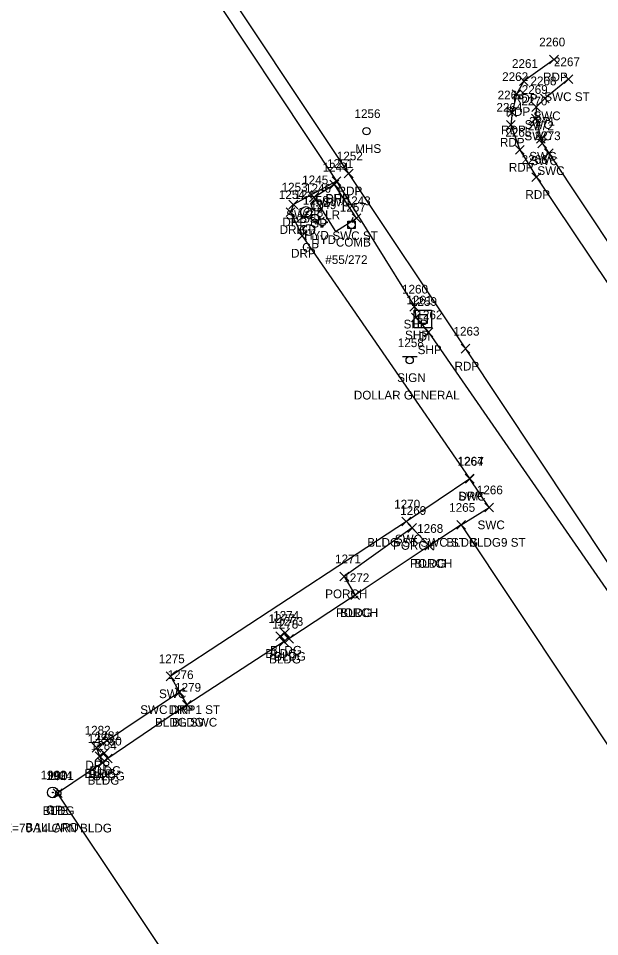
# Model space of a CAD drawing. Extents: x 1635588 to 1637550, y 621583 to 623638.
# Drawn here: x 1636661.5 to 1636794.5, y 622475 to 622685.3 of the extents above; entities that cross this region are included whole.
import ezdxf

# ---------------------------------------------------------------- set-up
doc = ezdxf.new("R2010")
doc.units = 0
for name, color, linetype in [('C_A', 7, 'Continuous'), ('C_C', 7, 'Continuous'), ('C_I', 7, 'Continuous'), ('CBP', 7, 'Continuous'), ('D_A', 7, 'Continuous'), ('D_I', 7, 'Continuous'), ('DS', 7, 'Continuous'), ('L_A', 7, 'Continuous'), ('L_I', 7, 'Continuous'), ('L_TIC', 7, 'Continuous'), ('LBC', 7, 'Continuous'), ('LBF', 7, 'Continuous'), ('P_A', 7, 'Continuous'), ('P_I', 7, 'Continuous'), ('P_TIC', 7, 'Continuous'), ('PET', 7, 'Continuous'), ('PSP', 7, 'Continuous'), ('R_A', 7, 'Continuous'), ('R_C', 7, 'Continuous'), ('R_I', 7, 'Continuous'), ('R_TIC', 7, 'Continuous'), ('RDP', 7, 'Continuous'), ('RGP', 7, 'Continuous'), ('RSW', 7, 'Continuous'), ('S_A', 7, 'Continuous'), ('S_C', 7, 'Continuous'), ('S_I', 7, 'Continuous'), ('SSGN', 7, 'Continuous'), ('U_A', 7, 'Continuous'), ('U_C', 7, 'Continuous'), ('U_I', 7, 'Continuous'), ('UP', 7, 'Continuous'), ('USMH', 7, 'Continuous'), ('UWFH', 7, 'Continuous')]:
    doc.layers.add(name, color=color, linetype=linetype)

msp = doc.modelspace()

# ---------------------------------------------------------------- linework, layer by layer
at = {"layer": 'CBP'}
for radius in [0.625, 0.0833]:
    msp.add_circle((1636670.59, 622507.85), radius, dxfattribs=at)
at = {"layer": 'DS'}
for p, q in [((1636752.05, 622618.47), (1636756.05, 622618.47)), ((1636752.05, 622614.47), (1636752.05, 622618.47)), ((1636756.05, 622618.47), (1636756.05, 622614.47)), ((1636753.05, 622615.47), (1636753.05, 622617.47)), ((1636753.05, 622617.47), (1636755.05, 622617.47)), ((1636754.06, 622616.47), (1636754.06, 622616.47)), ((1636754.06, 622616.47), (1636754.06, 622616.47)), ((1636755.05, 622617.47), (1636755.05, 622615.47)), ((1636756.05, 622614.47), (1636752.05, 622614.47)), ((1636755.05, 622615.47), (1636753.05, 622615.47))]:
    msp.add_line(p, q, dxfattribs=at)
at = {"layer": 'L_TIC'}
for points in [[(1636750.64, 622567.6), (1636752.64, 622569.6)], [(1636752.64, 622567.6), (1636750.64, 622569.6)], [(1636761.84, 622568.3), (1636763.84, 622570.3)], [(1636763.84, 622568.3), (1636761.84, 622570.3)], [(1636761.84, 622568.3), (1636763.84, 622570.3)], [(1636763.84, 622568.3), (1636761.84, 622570.3)], [(1636754.52, 622563.48), (1636756.52, 622565.48)], [(1636756.52, 622563.48), (1636754.52, 622565.48)], [(1636754.52, 622563.48), (1636756.52, 622565.48)], [(1636756.52, 622563.48), (1636754.52, 622565.48)], [(1636735.09, 622556.51), (1636737.09, 622558.51)], [(1636737.09, 622556.51), (1636735.09, 622558.51)], [(1636737.55, 622552.19), (1636739.55, 622554.19)], [(1636739.55, 622552.19), (1636737.55, 622554.19)], [(1636737.55, 622552.19), (1636739.55, 622554.19)], [(1636739.55, 622552.19), (1636737.55, 622554.19)], [(1636720.44, 622542.84), (1636722.44, 622544.84)], [(1636722.44, 622542.84), (1636720.44, 622544.84)], [(1636721.51, 622543.58), (1636723.51, 622545.58)], [(1636723.51, 622543.58), (1636721.51, 622545.58)], [(1636722.42, 622542.2), (1636724.42, 622544.2)], [(1636724.42, 622542.2), (1636722.42, 622544.2)], [(1636721.28, 622541.56), (1636723.28, 622543.56)], [(1636723.28, 622541.56), (1636721.28, 622543.56)], [(1636699.04, 622527.09), (1636701.04, 622529.09)], [(1636701.04, 622527.09), (1636699.04, 622529.09)], [(1636679.01, 622515.34), (1636681.01, 622517.34)], [(1636681.01, 622515.34), (1636679.01, 622517.34)], [(1636680.11, 622516.02), (1636682.11, 622518.02)], [(1636682.11, 622516.02), (1636680.11, 622518.02)], [(1636679.71, 622513.78), (1636681.71, 622515.78)], [(1636681.71, 622513.78), (1636679.71, 622515.78)], [(1636680.95, 622514.77), (1636682.95, 622516.77)], [(1636682.95, 622514.77), (1636680.95, 622516.77)], [(1636669.45, 622506.84), (1636671.45, 622508.84)], [(1636671.45, 622506.84), (1636669.45, 622508.84)]]:
    msp.add_lwpolyline(points, dxfattribs=at)
at = {"layer": 'LBC'}
for points in [[(1636762.84, 622569.3), (1636755.52, 622564.48), (1636738.55, 622553.19), (1636723.42, 622543.2), (1636722.51, 622544.58), (1636721.44, 622543.84), (1636722.28, 622542.56), (1636700.04, 622528.09), (1636681.95, 622515.77), (1636681.11, 622517.02), (1636680.01, 622516.34), (1636680.71, 622514.78)], [(1636762.84, 622569.3), (1636812.75, 622494.27), (1636839.75, 622454.02), (1636807.39, 622432.4)], [(1636680.71, 622514.78), (1636670.45, 622507.84)], [(1636729.47, 622348.39), (1636714.18, 622370.82), (1636701.75, 622403.63), (1636688.1, 622440.06), (1636687.15, 622442.65), (1636702.92, 622453.14), (1636705.64, 622455.02), (1636670.45, 622507.84)]]:
    msp.add_lwpolyline(points, dxfattribs=at)
at = {"layer": 'LBF'}
msp.add_lwpolyline([(1636755.52, 622564.48), (1636751.64, 622568.6), (1636736.09, 622557.51), (1636738.55, 622553.19)], dxfattribs=at)
at = {"layer": 'P_TIC'}
for points in [[(1636783.1, 622674.92), (1636785.1, 622676.92)], [(1636785.1, 622674.92), (1636783.1, 622676.92)], [(1636776.21, 622669.99), (1636778.21, 622671.99)], [(1636778.21, 622669.99), (1636776.21, 622671.99)], [(1636774.52, 622666.99), (1636776.52, 622668.99)], [(1636776.52, 622666.99), (1636774.52, 622668.99)], [(1636773.5, 622662.78), (1636775.5, 622664.78)], [(1636775.5, 622662.78), (1636773.5, 622664.78)], [(1636773.23, 622659.96), (1636775.23, 622661.96)], [(1636775.23, 622659.96), (1636773.23, 622661.96)], [(1636775.27, 622654.22), (1636777.27, 622656.22)], [(1636777.27, 622654.22), (1636775.27, 622656.22)], [(1636736.08, 622648.81), (1636738.08, 622650.81)], [(1636738.08, 622648.81), (1636736.08, 622650.81)], [(1636779.06, 622647.99), (1636781.06, 622649.99)], [(1636781.06, 622647.99), (1636779.06, 622649.99)], [(1636733.28, 622647.07), (1636735.28, 622649.07)], [(1636735.28, 622647.07), (1636733.28, 622649.07)], [(1636751.12, 622618.3), (1636753.12, 622620.3)], [(1636753.12, 622618.3), (1636751.12, 622620.3)], [(1636751.46, 622615.81), (1636753.46, 622617.81)], [(1636753.46, 622615.81), (1636751.46, 622617.81)], [(1636754.34, 622612.42), (1636756.34, 622614.42)], [(1636756.34, 622612.42), (1636754.34, 622614.42)], [(1636762.83, 622608.67), (1636764.83, 622610.67)], [(1636764.83, 622608.67), (1636762.83, 622610.67)]]:
    msp.add_lwpolyline(points, dxfattribs=at)
at = {"layer": 'PET'}
for points in [[(1636496.54, 623045.3), (1636533.69, 622970.65), (1636546.95, 622944.69), (1636557.06, 622926.23), (1636579, 622887.89), (1636603.72, 622849.48), (1636616.07, 622830.82), (1636647.79, 622783.76), (1636703.25, 622700.68), (1636737.08, 622649.81), (1636763.83, 622609.67), (1636812.95, 622535.62), (1636858.06, 622468.21), (1636878.24, 622438.26), (1636911.18, 622389.38), (1636974.88, 622293.33), (1636986.61, 622276.7), (1637016.63, 622231.99)], [(1636784.1, 622675.92), (1636777.21, 622670.99), (1636775.52, 622667.99), (1636774.5, 622663.78), (1636774.23, 622660.96), (1636776.27, 622655.22), (1636780.06, 622648.99), (1636825.5, 622581.26), (1636877.35, 622502.82), (1636883.38, 622494.85), (1636885.53, 622493.24), (1636887.72, 622493), (1636889.89, 622493.88)]]:
    msp.add_lwpolyline(points, dxfattribs=at)
at = {"layer": 'PSP'}
msp.add_lwpolyline([(1636412.61, 623220.07), (1636436.6, 623167.3), (1636456.23, 623125.07), (1636460.67, 623115.98), (1636475.52, 623084.87), (1636494.51, 623045.42), (1636524.16, 622986.51), (1636530.74, 622972.24), (1636554.07, 622925.3), (1636577.18, 622886.3), (1636601.72, 622847.41), (1636613.46, 622830.09), (1636645.38, 622782.47), (1636700.61, 622698.86), (1636734.28, 622648.07), (1636752.12, 622619.3), (1636752.46, 622616.81), (1636755.34, 622613.42), (1636810.04, 622534.39), (1636855.63, 622465.66), (1636874.76, 622437.49), (1636904.15, 622393.55)], dxfattribs=at)
at = {"layer": 'R_TIC'}
for points in [[(1636786.39, 622670.39), (1636788.39, 622672.39)], [(1636788.39, 622670.39), (1636786.39, 622672.39)], [(1636781.02, 622666.01), (1636783.02, 622668.01)], [(1636783.02, 622666.01), (1636781.02, 622668.01)], [(1636779.03, 622664.03), (1636781.03, 622666.03)], [(1636781.03, 622664.03), (1636779.03, 622666.03)], [(1636778.97, 622661.41), (1636780.97, 622663.41)], [(1636780.97, 622661.41), (1636778.97, 622663.41)], [(1636780.07, 622656.75), (1636782.07, 622658.75)], [(1636782.07, 622656.75), (1636780.07, 622658.75)], [(1636780.38, 622655.72), (1636782.38, 622657.72)], [(1636782.38, 622655.72), (1636780.38, 622657.72)], [(1636781.93, 622653.45), (1636783.93, 622655.45)], [(1636783.93, 622653.45), (1636781.93, 622655.45)], [(1636732.81, 622646.26), (1636734.81, 622648.26)], [(1636734.81, 622646.26), (1636732.81, 622648.26)], [(1636733.28, 622647.07), (1636735.28, 622649.07)], [(1636735.28, 622647.07), (1636733.28, 622649.07)], [(1636728.15, 622643.34), (1636730.15, 622645.34)], [(1636730.15, 622643.34), (1636728.15, 622645.34)], [(1636723.42, 622641.67), (1636725.42, 622643.67)], [(1636725.42, 622641.67), (1636723.42, 622643.67)], [(1636722.79, 622639.96), (1636724.79, 622641.96)], [(1636724.79, 622639.96), (1636722.79, 622641.96)], [(1636737.86, 622638.54), (1636739.86, 622640.54)], [(1636739.86, 622638.54), (1636737.86, 622640.54)], [(1636725.41, 622634.54), (1636727.41, 622636.54)], [(1636727.41, 622634.54), (1636725.41, 622636.54)], [(1636763.74, 622578.91), (1636765.74, 622580.91)], [(1636765.74, 622578.91), (1636763.74, 622580.91)], [(1636763.82, 622578.85), (1636765.82, 622580.85)], [(1636765.82, 622578.85), (1636763.82, 622580.85)], [(1636768.23, 622572.31), (1636770.23, 622574.31)], [(1636770.23, 622572.31), (1636768.23, 622574.31)], [(1636749.29, 622569.06), (1636751.29, 622571.06)], [(1636751.29, 622569.06), (1636749.29, 622571.06)], [(1636761.84, 622568.3), (1636763.84, 622570.3)], [(1636763.84, 622568.3), (1636761.84, 622570.3)], [(1636695.29, 622533.62), (1636697.29, 622535.62)], [(1636697.29, 622533.62), (1636695.29, 622535.62)], [(1636697.36, 622529.98), (1636699.36, 622531.98)], [(1636699.36, 622529.98), (1636697.36, 622531.98)], [(1636697.36, 622529.98), (1636699.36, 622531.98)], [(1636699.36, 622529.98), (1636697.36, 622531.98)], [(1636699.04, 622527.09), (1636701.04, 622529.09)], [(1636701.04, 622527.09), (1636699.04, 622529.09)], [(1636678.32, 622517.27), (1636680.32, 622519.27)], [(1636680.32, 622517.27), (1636678.32, 622519.27)], [(1636679.01, 622515.34), (1636681.01, 622517.34)], [(1636681.01, 622515.34), (1636679.01, 622517.34)]]:
    msp.add_lwpolyline(points, dxfattribs=at)
at = {"layer": 'RDP'}
for points in [[(1636734.28, 622648.07), (1636724.42, 622642.67), (1636723.79, 622640.96), (1636726.41, 622635.54), (1636764.74, 622579.91)], [(1636698.36, 622530.98), (1636679.32, 622518.27), (1636680.01, 622516.34)]]:
    msp.add_lwpolyline(points, dxfattribs=at)
at = {"layer": 'RGP'}
for p, q in [((1636727.33, 622640.97), (1636727.33, 622640.97)), ((1636729.85, 622642.41), (1636729.85, 622642.41)), ((1636728, 622636.88), (1636728, 622636.88)), ((1636669.34, 622508.01), (1636669.34, 622508.01))]:
    msp.add_line(p, q, dxfattribs=at)
for centre, radius in [((1636729.85, 622642.41), 1.25), ((1636727.33, 622640.97), 1.25), ((1636727.33, 622640.97), 0.0833), ((1636729.85, 622642.41), 0.0833), ((1636728, 622636.88), 1.25), ((1636728, 622636.88), 0.0833), ((1636669.34, 622508.01), 1.25), ((1636669.34, 622508.01), 0.0833)]:
    msp.add_circle(centre, radius, dxfattribs=at)
at = {"layer": 'RSW'}
for points in [[(1636787.39, 622671.39), (1636782.02, 622667.01), (1636780.03, 622665.03), (1636779.97, 622662.41), (1636781.07, 622657.75), (1636781.38, 622656.72), (1636782.93, 622654.45), (1636829.77, 622583.89), (1636881.88, 622505.96)], [(1636738.86, 622639.54), (1636733.81, 622647.26), (1636729.15, 622644.34), (1636734.04, 622636.52), (1636738.86, 622639.54)], [(1636762.84, 622569.3), (1636769.23, 622573.31), (1636764.82, 622579.85), (1636750.29, 622570.06), (1636696.29, 622534.62), (1636698.36, 622530.98), (1636700.04, 622528.09)]]:
    msp.add_lwpolyline(points, dxfattribs=at)
at = {"layer": 'SSGN'}
for p, q in [((1636749.4, 622607.88), (1636752.74, 622607.88)), ((1636751.05, 622607.05), (1636751.05, 622607.05))]:
    msp.add_line(p, q, dxfattribs=at)
msp.add_circle((1636751.05, 622607.05), 0.833, dxfattribs=at)
at = {"layer": 'UP'}
for p, q in [((1636736.93, 622637.24), (1636736.93, 622638.9)), ((1636736.93, 622638.9), (1636738.59, 622638.9)), ((1636738.01, 622639.74), (1636737.76, 622638.9)), ((1636738.59, 622638.9), (1636738.59, 622637.24)), ((1636738.59, 622637.24), (1636736.93, 622637.24)), ((1636737.51, 622636.4), (1636737.76, 622637.24)), ((1636737.76, 622638.07), (1636737.76, 622638.07))]:
    msp.add_line(p, q, dxfattribs=at)
msp.add_circle((1636737.76, 622638.07), 0.833, dxfattribs=at)
at = {"layer": 'USMH'}
for p, q in [((1636741.17, 622659.51), (1636741.17, 622659.51)), ((1636742, 622659.51), (1636742, 622659.51))]:
    msp.add_line(p, q, dxfattribs=at)
msp.add_circle((1636741.17, 622659.51), 0.833, dxfattribs=at)
at = {"layer": 'UWFH'}
for p, q in [((1636729.38, 622639.65), (1636729.38, 622639.65)), ((1636731.02, 622638.64), (1636731.02, 622638.64))]:
    msp.add_line(p, q, dxfattribs=at)
for centre, radius in [((1636728.38, 622639.65), 0.167), ((1636729.38, 622639.65), 0.833), ((1636731.02, 622638.64), 0.833), ((1636730.38, 622639.65), 0.167), ((1636729.38, 622638.65), 0.167), ((1636730.02, 622638.64), 0.167), ((1636731.02, 622637.64), 0.167), ((1636732.02, 622638.64), 0.167)]:
    msp.add_circle(centre, radius, dxfattribs=at)

# ---------------------------------------------------------------- texts
at = {"layer": 'C_A'}
msp.add_text('TIE', height=2, dxfattribs=at).set_placement((1636668.67, 622502.85))
at = {"layer": 'C_C'}
msp.add_text('TIE=70.14 CRN BLDG', height=2, dxfattribs=at).set_placement((1636655.89, 622498.85))
at = {"layer": 'C_I'}
msp.add_text('1904', height=2, dxfattribs=at).set_placement((1636667.82, 622510.85))
at = {"layer": 'D_A'}
msp.add_text('DI', height=2, dxfattribs=at).set_placement((1636753.11, 622611.47))
at = {"layer": 'D_I'}
msp.add_text('1259', height=2, dxfattribs=at).set_placement((1636751.36, 622619.47))
at = {"layer": 'L_A'}
for s, p in [('PORCH', (1636747.26, 622563.6)), ('BLDG', (1636759.43, 622564.3)), ('BLDG', (1636759.43, 622564.3)), ('PORCH', (1636751.14, 622559.48)), ('BLDG', (1636752.11, 622559.48)), ('PORCH', (1636731.71, 622552.51)), ('PORCH', (1636734.18, 622548.19)), ('BLDG', (1636735.14, 622548.19)), ('BLDG', (1636718.03, 622538.84)), ('BLDG', (1636719.1, 622539.58)), ('BLDG', (1636720.01, 622538.2)), ('BLDG', (1636718.87, 622537.56)), ('BLDG', (1636696.63, 622523.09)), ('BLDG', (1636676.6, 622511.34)), ('BLDG', (1636677.7, 622512.02)), ('BLDG', (1636678.54, 622510.77)), ('BLDG', (1636677.3, 622509.78)), ('BLDG', (1636667.04, 622502.84))]:
    msp.add_text(s, height=2, dxfattribs=at).set_placement(p)
at = {"layer": 'L_I'}
for s, p in [('1265', (1636760.1, 622572.3)), ('1265', (1636760.1, 622572.3)), ('1269', (1636748.89, 622571.6)), ('1268', (1636752.78, 622567.48)), ('1268', (1636752.78, 622567.48)), ('1271', (1636733.96, 622560.51)), ('1272', (1636735.86, 622556.19)), ('1272', (1636735.86, 622556.19)), ('1277', (1636718.74, 622546.84)), ('1274', (1636719.81, 622547.58)), ('1278', (1636719.59, 622545.56)), ('1273', (1636720.73, 622546.2)), ('1279', (1636697.34, 622531.09)), ('1283', (1636677.32, 622519.34)), ('1281', (1636678.98, 622520.02)), ('1284', (1636678.01, 622517.78)), ('1280', (1636679.17, 622518.77)), ('1901', (1636668.25, 622510.84))]:
    msp.add_text(s, height=2, dxfattribs=at).set_placement(p)
at = {"layer": 'P_A'}
for s, p in [('RDP', (1636781.59, 622670.92)), ('RDP', (1636774.7, 622665.99)), ('RDP', (1636773.01, 622662.99)), ('RDP', (1636771.99, 622658.78)), ('RDP', (1636771.71, 622655.96)), ('RDP', (1636773.76, 622650.22)), ('RDP', (1636734.56, 622644.81)), ('RDP', (1636777.54, 622643.99)), ('SHP', (1636731.82, 622643.07)), ('SHP', (1636749.66, 622614.3)), ('SHP', (1636749.99, 622611.81)), ('SHP', (1636752.88, 622608.42)), ('RDP', (1636761.32, 622604.67))]:
    msp.add_text(s, height=2, dxfattribs=at).set_placement(p)
at = {"layer": 'P_I'}
for s, p in [('2260', (1636780.71, 622678.92)), ('2261', (1636774.47, 622673.99)), ('2262', (1636772.22, 622670.99)), ('2263', (1636771.19, 622666.78)), ('2264', (1636770.92, 622663.96)), ('2265', (1636772.96, 622658.22)), ('1252', (1636734.38, 622652.81)), ('2266', (1636776.69, 622651.99)), ('1251', (1636732.15, 622651.07)), ('1260', (1636749.3, 622622.3)), ('1261', (1636750.28, 622619.81)), ('1262', (1636752.6, 622616.42)), ('1263', (1636761.09, 622612.67))]:
    msp.add_text(s, height=2, dxfattribs=at).set_placement(p)
at = {"layer": 'R_A'}
for s, p in [('SWC ST', (1636781.88, 622666.39)), ('SWC', (1636777.39, 622660.03)), ('SWC', (1636779.38, 622662.01)), ('SWC', (1636777.33, 622657.41)), ('SWC', (1636778.43, 622652.75)), ('SWC', (1636778.75, 622651.72)), ('SWC', (1636780.29, 622649.45)), ('SWC', (1636731.17, 622642.26)), ('DRP', (1636731.77, 622643.07)), ('SWC CLR', (1636722.78, 622639.34)), ('DRP', (1636721.91, 622637.67)), ('GP', (1636728.29, 622637.41)), ('DRP', (1636721.28, 622635.96)), ('GP', (1636725.76, 622635.97)), ('SWC ST', (1636733.36, 622634.54)), ('DRP', (1636723.9, 622630.54)), ('GP', (1636726.44, 622631.88)), ('SWC', (1636762.18, 622574.85)), ('DRP', (1636762.23, 622574.91)), ('SWC', (1636766.59, 622568.31)), ('BLDG ST SWC ST BLDG9 ST', (1636741.34, 622564.3)), ('SWC', (1636747.65, 622565.06)), ('SWC', (1636693.66, 622529.62)), ('SWC DRP1 ST', (1636689.36, 622525.98)), ('DRP', (1636695.85, 622525.98)), ('BLDG SWC', (1636692.73, 622523.09)), ('DRP', (1636676.81, 622513.27)), ('DRP', (1636677.5, 622511.34)), ('GP', (1636667.77, 622503.01))]:
    msp.add_text(s, height=2, dxfattribs=at).set_placement(p)
at = {"layer": 'R_C'}
msp.add_text('BALLARD', height=2, dxfattribs=at).set_placement((1636663.08, 622499.01))
at = {"layer": 'R_I'}
for s, p in [('2267', (1636784.08, 622674.39)), ('2268', (1636778.71, 622670.01)), ('2269', (1636776.71, 622668.03)), ('2270', (1636776.63, 622665.41)), ('2271', (1636778.38, 622660.75)), ('2272', (1636778.12, 622659.72)), ('2273', (1636779.67, 622657.45)), ('1244', (1636731.12, 622650.26)), ('1251', (1636732.15, 622651.07)), ('1245', (1636726.45, 622647.34)), ('1253', (1636721.73, 622645.67)), ('1246', (1636727.1, 622645.41)), ('1254', (1636721.1, 622643.96)), ('1247', (1636724.64, 622643.97)), ('1243', (1636736.17, 622642.54)), ('1248', (1636725.31, 622639.88)), ('1255', (1636723.72, 622638.54)), ('1264', (1636762, 622582.91)), ('1267', (1636762.08, 622582.85)), ('1266', (1636766.43, 622576.31)), ('1270', (1636747.51, 622573.06)), ('1265', (1636760.1, 622572.3)), ('1275', (1636693.6, 622537.62)), ('1276', (1636695.62, 622533.98)), ('1276', (1636695.62, 622533.98)), ('1279', (1636697.34, 622531.09)), ('1282', (1636676.63, 622521.27)), ('1283', (1636677.32, 622519.34)), ('1902', (1636666.56, 622511.01))]:
    msp.add_text(s, height=2, dxfattribs=at).set_placement(p)
at = {"layer": 'S_A'}
msp.add_text('SIGN', height=2, dxfattribs=at).set_placement((1636748.19, 622602.03))
at = {"layer": 'S_C'}
msp.add_text('DOLLAR GENERAL', height=2, dxfattribs=at).set_placement((1636738.27, 622598.03))
at = {"layer": 'S_I'}
msp.add_text('1258', height=2, dxfattribs=at).set_placement((1636748.34, 622610.03))
at = {"layer": 'U_A'}
for s, p in [('MHS', (1636738.59, 622654.51)), ('HYD', (1636726.9, 622634.65)), ('HYD', (1636728.54, 622633.64)), ('COMB', (1636734.15, 622633.07))]:
    msp.add_text(s, height=2, dxfattribs=at).set_placement(p)
at = {"layer": 'U_C'}
msp.add_text('#55/272', height=2, dxfattribs=at).set_placement((1636731.73, 622629.07))
at = {"layer": 'U_I'}
for s, p in [('1256', (1636738.42, 622662.51)), ('1250', (1636726.6, 622642.65)), ('1249', (1636728.32, 622641.64)), ('1257', (1636735.07, 622641.07))]:
    msp.add_text(s, height=2, dxfattribs=at).set_placement(p)

doc.saveas('drawing.dxf')
